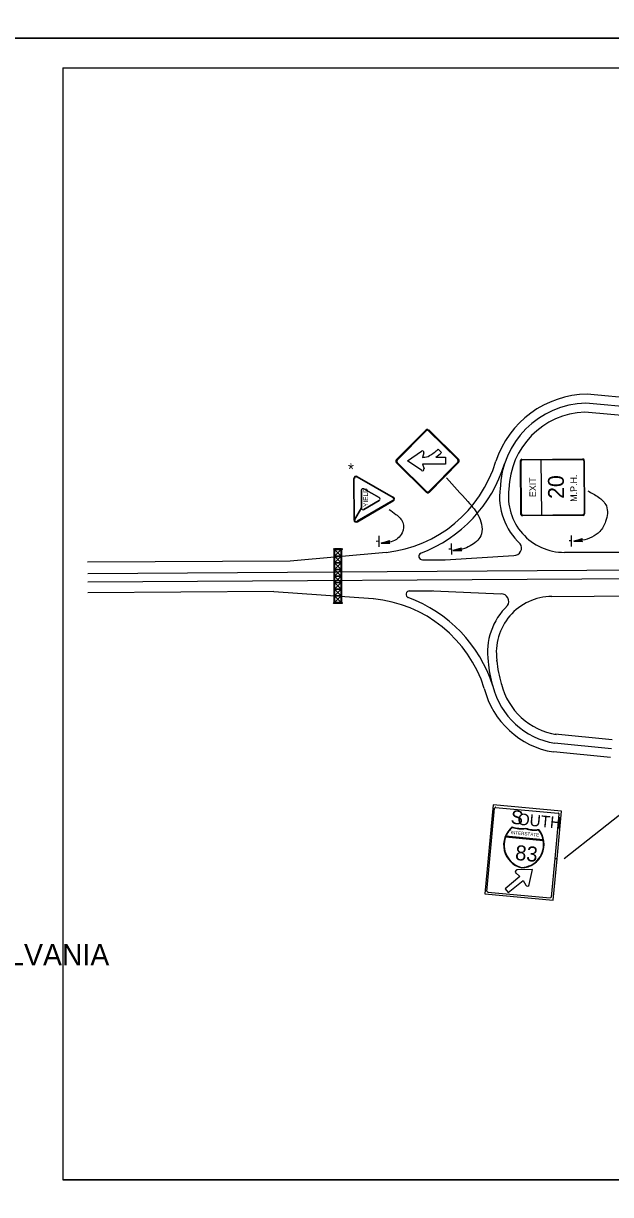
# Model space of a CAD drawing. Extents: x 644898 to 648326, y 298294 to 300670.
# Drawn here: x 646600 to 646898, y 299490 to 300084 of the extents above; entities that cross this region are included whole.
import ezdxf

# ---------------------------------------------------------------- set-up
doc = ezdxf.new("R2010")
doc.units = 0
for name, color, linetype in [('1', 7, 'Continuous'), ('2', 7, 'Continuous'), ('XCS-GRID-MIN', 7, 'Continuous')]:
    doc.layers.add(name, color=color, linetype=linetype)

msp = doc.modelspace()

# ---------------------------------------------------------------- linework, layer by layer
at = {"layer": '1'}
for p, q in [((646620.32, 300061.49), (647406.32, 300061.49)), ((646620.32, 300061.49), (646620.32, 299497.49)), ((647406.32, 299497.49), (646620.32, 299497.49)), ((646620.32, 299497.49), (647206.32, 299497.49))]:
    msp.add_line(p, q, dxfattribs=at)
at = {"layer": '2'}
for p, q in [((646915.57, 299893.12), (646886.41, 299895.9)), ((646914.7, 299884.12), (646885.14, 299886.91)), ((646915.07, 299888.62), (646885.65, 299891.41)), ((646789.45, 299862.62), (646804.57, 299877.87)), ((646789.95, 299862.49), (646804.57, 299877.37)), ((646805.82, 299877.37), (646820.7, 299862.74)), ((646805.95, 299877.87), (646821.2, 299862.74)), ((646795.2, 299862.12), (646802.32, 299867.12)), ((646795.2, 299862.12), (646802.32, 299867.12)), ((646803.45, 299866.24), (646802.82, 299863.87)), ((646803.45, 299866.24), (646802.82, 299863.87)), ((646802.82, 299863.87), (646803.2, 299863.99)), ((646802.82, 299863.87), (646803.2, 299863.99)), ((646809.57, 299863.99), (646814.45, 299863.99)), ((646809.57, 299863.99), (646809.57, 299863.99)), ((646809.57, 299863.99), (646814.45, 299863.99)), ((646810.7, 299867.99), (646812.45, 299866.37)), ((646810.7, 299867.99), (646812.45, 299866.37)), ((646814.45, 299863.99), (646814.45, 299860.37)), ((646814.45, 299863.99), (646814.45, 299860.37)), ((646853.2, 299862.87), (646884.2, 299863.12)), ((646804.82, 299846.12), (646789.45, 299861.24)), ((646804.82, 299846.62), (646789.95, 299861.24)), ((646802.45, 299857.24), (646795.2, 299862.12)), ((646802.45, 299857.24), (646795.2, 299862.12)), ((646814.45, 299860.37), (646802.82, 299860.37)), ((646802.82, 299860.37), (646803.57, 299858.12)), ((646814.45, 299860.37), (646802.82, 299860.37)), ((646802.82, 299860.37), (646803.57, 299858.12)), ((646820.7, 299861.49), (646806.07, 299846.62)), ((646821.2, 299861.49), (646806.2, 299846.12)), ((646852.7, 299834.99), (646852.57, 299862.24)), ((646853.07, 299835.24), (646852.82, 299861.99)), ((646853.45, 299862.74), (646883.95, 299862.87)), ((646863.32, 299834.62), (646863.07, 299862.74)), ((646884.57, 299862.24), (646884.82, 299835.37)), ((646884.82, 299862.37), (646884.95, 299835.24)), ((646768.07, 299832.24), (646767.95, 299853.12)), ((646768.32, 299832.24), (646768.2, 299853.12)), ((646768.32, 299832.24), (646768.2, 299853.12)), ((646769.45, 299853.99), (646787.7, 299843.49)), ((646769.45, 299853.99), (646787.7, 299843.49)), ((646769.7, 299854.12), (646787.95, 299843.74)), ((646771.82, 299838.24), (646771.82, 299847.12)), ((646771.82, 299847.12), (646771.82, 299838.24)), ((646773.07, 299847.87), (646780.82, 299843.49)), ((646780.82, 299843.49), (646773.07, 299847.87)), ((646787.82, 299841.99), (646769.7, 299831.49)), ((646787.82, 299841.99), (646769.7, 299831.49)), ((646787.95, 299841.74), (646769.82, 299831.12)), ((646780.82, 299841.99), (646773.07, 299837.49)), ((646773.07, 299837.49), (646780.82, 299841.99)), ((646771.82, 299838.24), (646768.32, 299832.24)), ((646768.32, 299832.24), (646771.82, 299838.24)), ((646771.82, 299838.24), (646771.82, 299838.24)), ((646884.32, 299834.49), (646853.45, 299834.24)), ((646884.2, 299834.74), (646853.57, 299834.49)), ((646780.57, 299824.12), (646780.57, 299818.49)), ((646878.2, 299824.24), (646878.2, 299818.74)), ((646735.57, 299811.49), (646784.32, 299815.74)), ((646758.2, 299817.12), (646761.57, 299813.74)), ((646761.57, 299817.12), (646758.2, 299813.74)), ((646780.57, 299821.37), (646779.32, 299821.24)), ((646817.45, 299817.37), (646816.2, 299817.37)), ((646817.32, 299820.24), (646817.45, 299814.62)), ((646874.82, 299815.74), (646933.07, 299815.99)), ((646874.82, 299815.74), (646874.82, 299815.74)), ((646878.2, 299821.49), (646877.2, 299821.49)), ((646632.9, 299810.93), (646735.57, 299811.49)), ((646758.2, 299813.74), (646761.57, 299810.49)), ((646761.57, 299813.74), (646758.2, 299810.49)), ((646758.2, 299810.49), (646761.57, 299806.99)), ((646761.57, 299810.49), (646758.2, 299806.99)), ((646802.82, 299811.87), (646814.32, 299811.99)), ((646814.32, 299811.99), (646849.2, 299814.12)), ((646932.2, 299806.74), (646632.96, 299804.85)), ((646758.2, 299806.99), (646761.57, 299803.62)), ((646761.57, 299806.99), (646758.2, 299803.62)), ((646633.01, 299800.83), (646931.82, 299802.62)), ((646758.2, 299803.62), (646761.57, 299800.37)), ((646761.57, 299803.62), (646758.2, 299800.37)), ((646758.2, 299800.37), (646761.57, 299796.99)), ((646761.57, 299800.37), (646758.2, 299796.99)), ((646727.35, 299795.86), (646633.07, 299795.24)), ((646727.35, 299795.86), (646777.82, 299792.24)), ((646758.2, 299796.99), (646761.57, 299793.62)), ((646761.57, 299796.99), (646758.2, 299793.62)), ((646758.2, 299793.62), (646761.57, 299790.24)), ((646761.57, 299793.62), (646758.2, 299790.24)), ((646761.57, 299790.24), (646761.57, 299793.62)), ((646796.2, 299796.12), (646807.82, 299796.24)), ((646808.4, 299796.21), (646796.2, 299796.12)), ((646808.4, 299796.21), (646842.57, 299794.62)), ((646930.95, 299793.62), (646868.32, 299793.24)), ((646872.7, 299793.24), (646872.7, 299793.24)), ((646840.57, 299760.62), (646840.57, 299760.99)), ((646842.82, 299748.87), (646842.82, 299749.24)), ((646899.07, 299720.62), (646870.07, 299723.49)), ((646898.7, 299716.12), (646869.7, 299718.99)), ((646898.2, 299711.74), (646869.32, 299714.49)), ((646874.72, 299660.52), (646937.82, 299710.3)), ((646838.64, 299687.74), (646834.39, 299642.49)), ((646835.51, 299643.74), (646839.39, 299685.99)), ((646873.39, 299684.47), (646838.64, 299687.74)), ((646839.89, 299686.36), (646871.63, 299683.49)), ((646872.01, 299682.99), (646869.95, 299660.44)), ((646871.05, 299660.33), (646873.39, 299684.47)), ((646844.96, 299671.5), (646864.08, 299669.63)), ((646864.08, 299669.88), (646845.08, 299671.75)), ((646869.93, 299660.44), (646868.14, 299640.84)), ((646869.01, 299639.24), (646871.05, 299660.33)), ((646871.05, 299660.33), (646869.93, 299660.44)), ((646869.95, 299660.44), (646871.05, 299660.33)), ((646852.21, 299651.25), (646844.71, 299645.13)), ((646852.21, 299651.25), (646844.71, 299645.13)), ((646846.33, 299643.13), (646853.83, 299649.25)), ((646846.33, 299643.13), (646853.83, 299649.25)), ((646850.08, 299653.13), (646852.21, 299651.25)), ((646850.08, 299653.13), (646852.21, 299651.25)), ((646858.58, 299654.88), (646850.71, 299654.75)), ((646858.58, 299654.88), (646850.71, 299654.75)), ((646853.83, 299649.25), (646855.21, 299646.88)), ((646853.83, 299649.25), (646855.21, 299646.88)), ((646856.83, 299647.25), (646858.58, 299654.88)), ((646856.83, 299647.25), (646858.58, 299654.88)), ((646844.71, 299645.13), (646846.33, 299643.13)), ((646844.71, 299645.13), (646846.33, 299643.13)), ((646856.96, 299647.25), (646856.83, 299647.25)), ((646856.96, 299647.25), (646856.83, 299647.25)), ((646834.39, 299642.49), (646869.01, 299639.24)), ((646867.63, 299640.36), (646836.01, 299643.24))]:
    msp.add_line(p, q, dxfattribs=at)
for points in [[(646785.97, 299820.41), (646785.86, 299820.67), (646781.8, 299820.42), (646785.97, 299820.41), (646786.17, 299820.26), (646781.8, 299820.42), (646785.8, 299821.2), (646785.86, 299821.47), (646781.8, 299820.42), (646786.1, 299821.76), (646785.86, 299821.47)], [(646883.71, 299821.32), (646883.6, 299821.58), (646879.54, 299821.33), (646883.71, 299821.32), (646883.91, 299821.16), (646879.54, 299821.33), (646883.54, 299822.1), (646883.6, 299822.38), (646879.54, 299821.33), (646883.84, 299822.67), (646883.6, 299822.38)], [(646757.82, 299817.12), (646757.82, 299790.24)], [(646761.57, 299817.49), (646758.2, 299817.49)], [(646758.2, 299790.24), (646761.57, 299790.24), (646761.57, 299817.12), (646758.2, 299817.12), (646758.2, 299790.24)], [(646761.95, 299790.24), (646761.95, 299817.12)], [(646822.53, 299816.72), (646822.41, 299816.98), (646818.35, 299816.73), (646822.53, 299816.72), (646822.72, 299816.56), (646818.35, 299816.73), (646822.36, 299817.5), (646822.42, 299817.78), (646818.35, 299816.73), (646822.65, 299818.07), (646822.42, 299817.78)], [(646758.2, 299789.87), (646761.57, 299789.87)]]:
    msp.add_lwpolyline(points, dxfattribs=at)
for points in [[(646758.2, 299813.74), (646758.2, 299817.12), (646761.57, 299817.12), (646761.57, 299813.74)], [(646758.2, 299810.49), (646758.2, 299813.74), (646761.57, 299813.74), (646761.57, 299810.49)], [(646758.2, 299806.99), (646758.2, 299810.49), (646761.57, 299810.49), (646761.57, 299806.99)], [(646758.2, 299803.62), (646758.2, 299806.99), (646761.57, 299806.99), (646761.57, 299803.62)], [(646758.2, 299800.37), (646758.2, 299803.62), (646761.57, 299803.62), (646761.57, 299800.37)], [(646758.2, 299796.99), (646758.2, 299800.37), (646761.57, 299800.37), (646761.57, 299796.99)], [(646758.2, 299793.62), (646758.2, 299796.99), (646761.57, 299796.99), (646761.57, 299793.62)], [(646758.2, 299790.24), (646758.2, 299793.62), (646761.57, 299793.62), (646761.57, 299790.24)]]:
    msp.add_lwpolyline(points, close=True, dxfattribs=at)
for centre in [(646758.02, 299817.33), (646761.8, 299817.33), (646758.02, 299790.03), (646761.8, 299790.03)]:
    msp.add_circle(centre, 0.301, dxfattribs=at)
for centre, radius, start, end in [((646886.86, 299846.67), 49.23, 90.52151, 161.98215), ((646886.86, 299846.67), 44.75, 91.54241, 178.50764), ((646886.86, 299846.67), 40.27, 92.44126, 178.50764), ((646805.23, 299877.17), 0.932, 45.37466, 135.37466), ((646805.24, 299876.78), 0.854, 45.37466, 135.37466), ((646802.71, 299866.44), 0.776, 344.17249, 122.04402), ((646802.71, 299866.44), 0.776, 344.17249, 122.04402), ((646803.19, 299870.23), 6.31, 270.15039, 300.26433), ((646803.19, 299870.23), 6.31, 270.15039, 300.26433), ((646795.5, 299883.74), 21.86, 299.81167, 314.25959), ((646795.5, 299883.74), 21.86, 299.81167, 314.25959), ((646795.08, 299884.24), 24.91, 305.51612, 314.26388), ((646795.08, 299884.24), 24.91, 305.51612, 314.26388), ((646777.21, 299880.98), 65.66, 276.25549, 343.10311), ((646790.17, 299861.91), 0.932, 135.37466, 225.37466), ((646790.56, 299861.91), 0.854, 135.37466, 225.37466), ((646777.21, 299880.98), 70.14, 290.68251, 343.10311), ((646802.76, 299857.89), 0.777, 238.81766, 16.46446), ((646802.76, 299857.89), 0.777, 238.81766, 16.46446), ((646820.11, 299862.1), 0.854, 315.37466, 45.37466), ((646820.49, 299862.11), 0.932, 315.37466, 45.37466), ((646769.08, 299853.16), 1.18, 60.37464, 180.37465), ((646769.08, 299853.16), 0.871, 60.37462, 180.37465), ((646769.08, 299853.16), 0.871, 60.37462, 180.37465), ((646772.6, 299847.15), 0.871, 60.37472, 180.37465), ((646772.6, 299847.15), 0.871, 60.37472, 180.37465), ((646805.43, 299846.85), 0.932, 225.37466, 315.37466), ((646805.43, 299847.23), 0.854, 225.37466, 315.37466), ((646874.75, 299844.08), 32.86, 172.63332, 226.96477), ((646874.75, 299844.08), 28.38, 172.63332, 270.16952), ((646780.36, 299842.74), 0.871, 300.37466, 60.37464), ((646780.36, 299842.74), 0.871, 300.37466, 60.37464), ((646787.33, 299842.78), 0.871, 300.37466, 60.37464), ((646787.33, 299842.78), 0.871, 300.37466, 60.37464), ((646787.33, 299842.78), 1.18, 300.37468, 60.37462), ((646772.66, 299838.23), 0.871, 180.37465, 300.37458), ((646772.66, 299838.23), 0.871, 180.37465, 300.37458), ((646769.21, 299832.17), 1.18, 180.37465, 300.37466), ((646769.21, 299832.17), 0.871, 180.37465, 300.37468), ((646769.21, 299832.17), 0.871, 180.37465, 300.37468), ((646849.26, 299817.88), 3.76, 268.45533, 35.52245), ((646802.76, 299813.73), 1.81, 115.17809, 270.48453), ((646771.58, 299726.81), 65.66, 17.64524, 84.49287), ((646796.24, 299794.39), 1.81, 90.26383, 245.57027), ((646771.58, 299726.81), 70.14, 17.64524, 70.06585), ((646868.62, 299764.98), 28.38, 90.57884, 188.11504), ((646842.8, 299790.85), 3.76, 325.22591, 92.29303), ((646868.62, 299764.98), 32.86, 133.78359, 188.11504), ((646892.29, 299764.63), 56.37, 184.36376, 197.37504), ((646892.29, 299764.63), 51.89, 184.36376, 197.37504), ((646876.13, 299757.22), 43.27, 194.04995, 260.84709), ((646876.13, 299757.22), 38.79, 194.04995, 260.84709), ((646876.13, 299757.22), 34.31, 194.04995, 260.84709), ((646839.94, 299686.02), 0.42, 84.74199, 174.80568), ((646871.68, 299683.06), 0.42, 354.09386, 85.03026), ((646855.92, 299667.27), 11.97, 129.56625, 256.43614), ((646855.92, 299667.27), 11.72, 130.25861, 157.7735), ((646852.93, 299689.45), 13.76, 250.31621, 278.81628), ((646852.93, 299689.45), 14.01, 250.90674, 278.55521), ((646852.55, 299667.59), 11.97, 272.69635, 39.56625), ((646859.67, 299688.81), 14.01, 250.57728, 278.22575), ((646859.67, 299688.81), 13.76, 250.31621, 278.81628), ((646852.55, 299667.59), 11.72, 11.359, 38.87388), ((646855.92, 299667.27), 11.72, 159.0531, 256.43614), ((646852.55, 299667.59), 11.72, 272.69635, 10.07939), ((646850.75, 299653.79), 0.916, 89.42516, 230.09068), ((646850.75, 299653.79), 0.916, 89.42516, 230.09068), ((646836.07, 299643.78), 0.42, 175.13549, 263.8845), ((646856, 299647.36), 0.916, 207.81363, 351.72026), ((646856, 299647.36), 0.916, 207.81363, 351.72026)]:
    msp.add_arc(centre, radius, start, end, dxfattribs=at)
for centre, major_axis, ratio, start_param, end_param in [((646884.19, 299862.44), (-0.005, 0.717), 0.9, 4.712389, 6.283185), ((646853.22, 299862.23), (0.005, -0.717), 0.9, 3.141593, 4.712389), ((646853.41, 299862.02), (0.004, -0.657), 0.9, 3.141593, 4.712389), ((646884.01, 299862.22), (-0.004, 0.657), 0.9, 4.712389, 6.283185), ((646853.4, 299834.99), (0.005, -0.717), 0.9, 4.712389, 6.283185), ((646853.58, 299835.2), (0.004, -0.657), 0.9, 4.712389, 6.283185), ((646884.18, 299835.4), (-0.004, 0.657), 0.9, 3.141593, 4.712389), ((646884.37, 299835.19), (0.005, -0.717), 0.9, 0, 1.570796), ((646867.7, 299640.9), (-0.431, 0), 0.924248, 1.489344, 3.050933)]:
    msp.add_ellipse(centre, major_axis=major_axis, ratio=ratio, start_param=start_param, end_param=end_param, dxfattribs=at)
for points in [[(646814.95, 299853.49), (646825.82, 299841.49), (646831.57, 299833.49), (646832.32, 299824.12), (646827.02, 299819.03), (646822.97, 299817.34), (646820.67, 299817)], [(646886.7, 299846.87), (646892.1, 299843.75), (646896.07, 299839.24), (646895.7, 299831.37), (646892.82, 299826.37), (646883.88, 299821.83), (646880.77, 299821.45)], [(646785.82, 299837.49), (646789.32, 299834.99), (646792.82, 299830.87), (646792.45, 299825.62), (646790.32, 299822.87), (646786.82, 299821.12), (646784.12, 299820.61)]]:
    msp.add_spline(points, degree=3, dxfattribs=at)
at = {"layer": 'XCS-GRID-MIN'}
for points in [[(646580.32, 300670.49), (647421.32, 300670.49), (647421.32, 300076.49), (646580.32, 300076.49)], [(646580.32, 300076.49), (647421.32, 300076.49), (647421.32, 299482.49), (646580.32, 299482.49)]]:
    msp.add_lwpolyline(points, close=True, dxfattribs=at)

# ---------------------------------------------------------------- texts
at = {"layer": '1'}
msp.add_text('COMMONWEALTH OF PENNSYLVANIA', height=10.7828, dxfattribs=at).set_placement((646377.92, 299606.22))
at = {"layer": '2'}
msp.add_text('*', height=5.85, dxfattribs=at).set_placement((646764.98, 299855.03))
for s, height, rotation, p in [('EXIT', 3.387, 90.3745, (646860.45, 299843.74)), ('20', 8.061, 90.37458, (646874.57, 299842.87)), ('M.P.H.', 3.387, 90.37456, (646881.2, 299841.37)), ('YIELD', 2.383, 90.37383, (646775.19, 299838.74)), ('S', 6.97, 354.58165, (646847.35, 299678.13)), ('OUTH', 5.85, 354.56831, (646850.83, 299677.63)), ('INTERSTATE', 1.693, 354.56662, (646847.46, 299672.88)), ('83', 7.618, 354.56569, (646849.58, 299659.75))]:
    msp.add_text(s, height=height, rotation=rotation, dxfattribs=at).set_placement(p)

doc.saveas('drawing.dxf')
